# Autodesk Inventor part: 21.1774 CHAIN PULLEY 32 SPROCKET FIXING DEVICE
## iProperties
Created: 2007-05
Part Number: 21.1774 CHAIN PULLEY 32 SPROCKET FIXING DEVICE
Material: Steel
Document SubType Name: Modeling
Designer: Andy Moles
Density: 7.85 g/cm^3
Mass: 9.19791 g
Surface Area: 9.56006 cm^2
Volume: 1.17171 cm^3
Author: Andy Moles
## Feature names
1. Base1
